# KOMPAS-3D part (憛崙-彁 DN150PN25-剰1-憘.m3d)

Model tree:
1. Объединить компоненты:1  (labels: СЕНС-ПР DN150PN25-ДП1)
2. Эскиз:1
3. Операция выдавливания:1
     Расстояние 1 = 14
4. Фаска:1
     Угол = 45; Длина 1 = 2; Длина 2 = 2

Referenced files in D:\Савин\!СЕНСОР\3D для заказчика\!Новый перечень\СЕНС-ПР\3. СЕНС-ПР-ДП\DN150\СЕНС-ПР DN150PN25-ДП1\: СЕНС-ПР DN150PN25-ДП1.a3d
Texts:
  СЕНС-ПР DN150PN25-ДП1-СВ
  ООО НПП Сенсор
  Body Specification ( left align )
  Body Specificaton ( centered )
  СЕНС-ПР DN150PN25-ДП1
